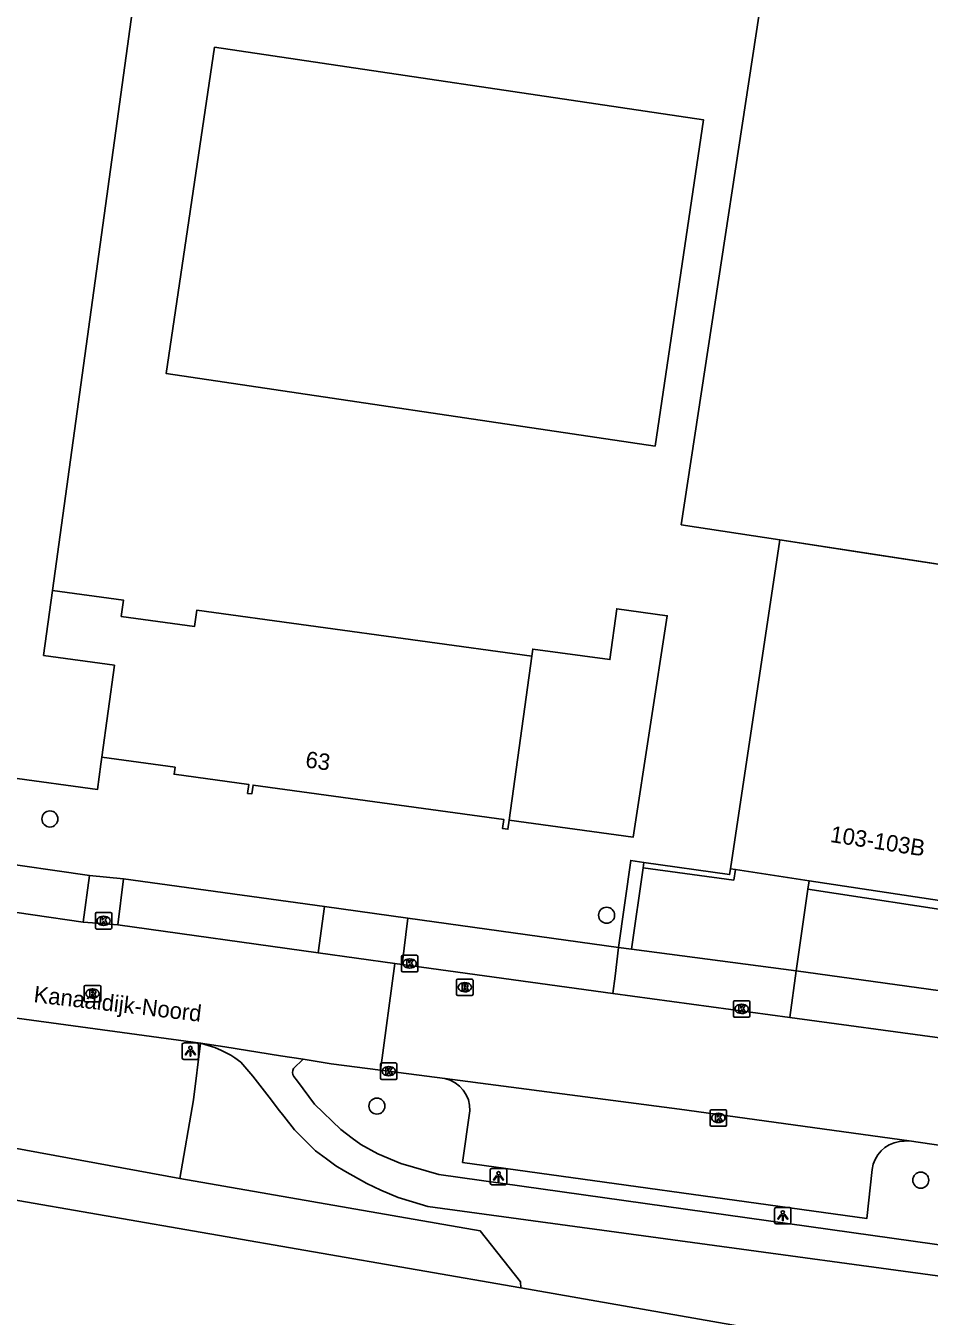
# Model space of a CAD drawing. Extents: x 163010 to 163853, y 382793 to 383982.
# Drawn here: x 163317.7 to 163372.7, y 382836.4 to 382915 of the extents above; entities that cross this region are included whole.
import ezdxf

# ---------------------------------------------------------------- set-up
doc = ezdxf.new("R2010")
doc.units = 0
for name, color, linetype in [('IMGEO_Boom', 7, 'Continuous'), ('IMGEO_Fietspad_open', 7, 'Continuous'), ('IMGEO_Groenvoorziening', 7, 'Continuous'), ('IMGEO_Hek', 7, 'Continuous'), ('IMGEO_Kolk', 7, 'Continuous'), ('IMGEO_Lichtpunt', 7, 'Continuous'), ('IMGEO_Muur', 7, 'Continuous'), ('IMGEO_Openbare_ruimte_label', 7, 'Continuous'), ('IMGEO_Pand', 7, 'Continuous'), ('IMGEO_Pand_nummerreeks', 7, 'Continuous'), ('IMGEO_Pand_vergunning_verleend', 7, 'Continuous'), ('IMGEO_Parkeervlak_gesloten', 7, 'Continuous'), ('IMGEO_Parkeervlak_open', 7, 'Continuous'), ('IMGEO_Rijbaan_lokaal_open', 7, 'Continuous'), ('IMGEO_Rioolput', 7, 'Continuous'), ('IMGEO_Voetpad_gesloten', 7, 'Continuous'), ('IMGEO_Voetpad_open', 7, 'Continuous'), ('IMGEO_Waterloop', 7, 'Continuous')]:
    doc.layers.add(name, color=color, linetype=linetype)

msp = doc.modelspace()

# ---------------------------------------------------------------- linework, layer by layer
at = {"layer": 'IMGEO_Boom'}
for centre in [(163319.165, 382866.647), (163353.055, 382860.785), (163339.071, 382849.16), (163372.178, 382844.649)]:
    msp.add_circle(centre, 0.489, dxfattribs=at)
at = {"layer": 'IMGEO_Fietspad_open'}
for points in [[(163328.342, 382852.995), (163328.799, 382852.856), (163329.201, 382852.719), (163329.62, 382852.555), (163330.175, 382852.263), (163330.426, 382852.1), (163330.779, 382851.826), (163331.276, 382851.256), (163331.516, 382850.98), (163332.653, 382849.515), (163333.07, 382848.976), (163333.412, 382848.539), (163334.065, 382847.703), (163335.332, 382846.43), (163335.997, 382845.943), (163336.58, 382845.516), (163337.125, 382845.189), (163338.464, 382844.438), (163339.318, 382844.032), (163340.356, 382843.584), (163341.233, 382843.336), (163342.164, 382843.039), (163390.211, 382836.499)], [(163333.993, 382851.453), (163334.575, 382852.01)], [(163499.251, 382822.021), (163494.803, 382822.681), (163390.478, 382838.302), (163342.832, 382844.985), (163340.526, 382845.669), (163339.133, 382846.245), (163338.098, 382846.827), (163337.562, 382847.213), (163336.875, 382847.731), (163335.282, 382849.281), (163334.239, 382850.672), (163334.016, 382850.97)]]:
    msp.add_lwpolyline(points, dxfattribs=at)
msp.add_arc((163334.367, 382851.229), 0.436, 149.04306, 216.40956, dxfattribs=at)
at = {"layer": 'IMGEO_Groenvoorziening'}
msp.add_lwpolyline([(163340.951, 382860.603), (163335.871, 382861.306)], dxfattribs=at)
at = {"layer": 'IMGEO_Hek'}
for points in [[(163353.778, 382858.828), (163354.529, 382864.119)], [(163354.529, 382864.119), (163355.327, 382864.004)]]:
    msp.add_lwpolyline(points, dxfattribs=at)
at = {"layer": 'IMGEO_Kolk'}
for p, q in [((163321.933, 382860.019), (163321.933, 382860.871)), ((163322.008, 382860.945), (163322.86, 382860.945)), ((163322.421, 382860.725), (163322.446, 382860.725)), ((163322.934, 382860.871), (163322.934, 382860.019)), ((163322.86, 382859.945), (163322.008, 382859.945)), ((163322.444, 382860.165), (163322.419, 382860.165)), ((163340.565, 382857.417), (163340.565, 382858.269)), ((163340.64, 382858.343), (163341.492, 382858.343)), ((163341.053, 382858.123), (163341.078, 382858.123)), ((163341.566, 382858.269), (163341.566, 382857.417)), ((163341.492, 382857.343), (163340.64, 382857.343)), ((163341.076, 382857.563), (163341.051, 382857.563)), ((163360.774, 382854.653), (163360.774, 382855.505)), ((163360.849, 382855.579), (163361.701, 382855.579)), ((163361.262, 382855.359), (163361.287, 382855.359)), ((163361.775, 382855.505), (163361.775, 382854.653)), ((163361.701, 382854.579), (163360.849, 382854.579)), ((163361.285, 382854.799), (163361.26, 382854.799)), ((163339.365, 382851.784), (163340.217, 382851.784)), ((163339.29, 382850.858), (163339.29, 382851.71)), ((163339.801, 382851.004), (163339.776, 382851.004)), ((163339.778, 382851.564), (163339.803, 382851.564)), ((163340.291, 382851.71), (163340.291, 382850.858)), ((163340.217, 382850.784), (163339.365, 382850.784)), ((163359.355, 382848.013), (163359.355, 382848.865)), ((163359.43, 382848.939), (163360.282, 382848.939)), ((163359.843, 382848.719), (163359.868, 382848.719)), ((163360.356, 382848.865), (163360.356, 382848.013)), ((163360.282, 382847.939), (163359.43, 382847.939)), ((163359.866, 382848.159), (163359.841, 382848.159))]:
    msp.add_line(p, q, dxfattribs=at)
for points in [[(163321.933, 382860.019), (163321.933, 382860.871)], [(163322.008, 382860.945), (163322.86, 382860.945)], [(163322.254, 382860.645), (163322.377, 382860.645), (163322.377, 382860.494), (163322.507, 382860.645), (163322.671, 382860.645), (163322.525, 382860.494), (163322.678, 382860.245), (163322.526, 382860.245), (163322.441, 382860.409), (163322.377, 382860.342), (163322.377, 382860.245), (163322.254, 382860.245), (163322.254, 382860.645)], [(163322.934, 382860.871), (163322.934, 382860.019)], [(163322.86, 382859.945), (163322.008, 382859.945)], [(163340.565, 382857.417), (163340.565, 382858.269)], [(163340.64, 382858.343), (163341.492, 382858.343)], [(163341.566, 382858.269), (163341.566, 382857.417)], [(163341.492, 382857.343), (163340.64, 382857.343)], [(163340.886, 382858.043), (163341.009, 382858.043), (163341.009, 382857.892), (163341.139, 382858.043), (163341.303, 382858.043), (163341.157, 382857.892), (163341.31, 382857.643), (163341.158, 382857.643), (163341.073, 382857.807), (163341.009, 382857.74), (163341.009, 382857.643), (163340.886, 382857.643), (163340.886, 382858.043)], [(163360.774, 382854.653), (163360.774, 382855.505)], [(163360.849, 382855.579), (163361.701, 382855.579)], [(163361.095, 382855.279), (163361.218, 382855.279), (163361.218, 382855.128), (163361.348, 382855.279), (163361.512, 382855.279), (163361.366, 382855.128), (163361.519, 382854.879), (163361.367, 382854.879), (163361.282, 382855.043), (163361.218, 382854.976), (163361.218, 382854.879), (163361.095, 382854.879), (163361.095, 382855.279)], [(163361.775, 382855.505), (163361.775, 382854.653)], [(163361.701, 382854.579), (163360.849, 382854.579)], [(163339.365, 382851.784), (163340.217, 382851.784)], [(163339.29, 382850.858), (163339.29, 382851.71)], [(163339.611, 382851.484), (163339.734, 382851.484), (163339.734, 382851.333), (163339.864, 382851.484), (163340.028, 382851.484), (163339.882, 382851.333), (163340.035, 382851.084), (163339.883, 382851.084), (163339.798, 382851.248), (163339.734, 382851.181), (163339.734, 382851.084), (163339.611, 382851.084), (163339.611, 382851.484)], [(163340.291, 382851.71), (163340.291, 382850.858)], [(163340.217, 382850.784), (163339.365, 382850.784)], [(163359.355, 382848.013), (163359.355, 382848.865)], [(163359.43, 382848.939), (163360.282, 382848.939)], [(163359.676, 382848.639), (163359.799, 382848.639), (163359.799, 382848.488), (163359.929, 382848.639), (163360.093, 382848.639), (163359.947, 382848.488), (163360.1, 382848.239), (163359.948, 382848.239), (163359.863, 382848.403), (163359.799, 382848.336), (163359.799, 382848.239), (163359.676, 382848.239), (163359.676, 382848.639)], [(163360.356, 382848.865), (163360.356, 382848.013)], [(163360.282, 382847.939), (163359.43, 382847.939)]]:
    msp.add_lwpolyline(points, dxfattribs=at)
for centre, start, end in [((163322.01, 382860.869), 91.55205, 178.44795), ((163322.01, 382860.869), 91.55205, 178.44795), ((163322.858, 382860.869), 1.55205, 88.44795), ((163322.858, 382860.869), 1.55205, 88.44795), ((163322.01, 382860.021), 181.55205, 268.44795), ((163322.01, 382860.021), 181.55205, 268.44795), ((163322.858, 382860.021), 271.55205, 358.44795), ((163322.858, 382860.021), 271.55205, 358.44795), ((163340.642, 382858.267), 91.55205, 178.44795), ((163340.642, 382858.267), 91.55205, 178.44795), ((163341.49, 382858.267), 1.55205, 88.44795), ((163341.49, 382858.267), 1.55205, 88.44795), ((163340.642, 382857.419), 181.55205, 268.44795), ((163340.642, 382857.419), 181.55205, 268.44795), ((163341.49, 382857.419), 271.55205, 358.44795), ((163341.49, 382857.419), 271.55205, 358.44795), ((163360.851, 382855.503), 91.55205, 178.44795), ((163360.851, 382855.503), 91.55205, 178.44795), ((163361.699, 382855.503), 1.55205, 88.44795), ((163361.699, 382855.503), 1.55205, 88.44795), ((163360.851, 382854.655), 181.55205, 268.44795), ((163360.851, 382854.655), 181.55205, 268.44795), ((163361.699, 382854.655), 271.55205, 358.44795), ((163361.699, 382854.655), 271.55205, 358.44795), ((163339.367, 382851.708), 91.55205, 178.44795), ((163339.367, 382851.708), 91.55205, 178.44795), ((163340.215, 382851.708), 1.55205, 88.44795), ((163340.215, 382851.708), 1.55205, 88.44795), ((163339.367, 382850.86), 181.55205, 268.44795), ((163339.367, 382850.86), 181.55205, 268.44795), ((163340.215, 382850.86), 271.55205, 358.44795), ((163340.215, 382850.86), 271.55205, 358.44795), ((163359.432, 382848.863), 91.55205, 178.44795), ((163359.432, 382848.863), 91.55205, 178.44795), ((163360.28, 382848.863), 1.55205, 88.44795), ((163360.28, 382848.863), 1.55205, 88.44795), ((163359.432, 382848.015), 181.55205, 268.44795), ((163359.432, 382848.015), 181.55205, 268.44795), ((163360.28, 382848.015), 271.55205, 358.44795), ((163360.28, 382848.015), 271.55205, 358.44795)]:
    msp.add_arc(centre, 0.0765, start, end, dxfattribs=at)
for centre, major_axis, ratio, start_param, end_param in [((163322.42, 382860.445), (-0.387, 0.002), 0.722429, 4.712389, 7.853982), ((163322.445, 382860.445), (-0.39, 0.002), 0.717154, 1.570796, 4.712389), ((163341.052, 382857.843), (-0.387, 0.002), 0.722429, 4.712389, 7.853982), ((163341.077, 382857.843), (-0.39, 0.002), 0.717154, 1.570796, 4.712389), ((163361.261, 382855.079), (-0.387, 0.002), 0.722429, 4.712389, 7.853982), ((163361.286, 382855.079), (-0.39, 0.002), 0.717154, 1.570796, 4.712389), ((163339.777, 382851.284), (-0.387, 0.002), 0.722429, 4.712389, 7.853982), ((163339.802, 382851.284), (-0.39, 0.002), 0.717154, 1.570796, 4.712389), ((163359.842, 382848.439), (-0.387, 0.002), 0.722429, 4.712389, 7.853982), ((163359.867, 382848.439), (-0.39, 0.002), 0.717154, 1.570796, 4.712389)]:
    msp.add_ellipse(centre, major_axis=major_axis, ratio=ratio, start_param=start_param, end_param=end_param, dxfattribs=at)
at = {"layer": 'IMGEO_Lichtpunt'}
for p, q in [((163327.219, 382852.907), (163327.219, 382852.1)), ((163327.219, 382852.907), (163327.219, 382852.1)), ((163328.121, 382853.002), (163327.313, 382853.002)), ((163328.121, 382853.002), (163327.313, 382853.002)), ((163328.215, 382852.1), (163328.215, 382852.907)), ((163328.215, 382852.1), (163328.215, 382852.907)), ((163327.313, 382852.006), (163328.121, 382852.006)), ((163327.313, 382852.006), (163328.121, 382852.006)), ((163345.976, 382845.27), (163345.976, 382844.463)), ((163345.976, 382845.27), (163345.976, 382844.463)), ((163346.878, 382845.365), (163346.07, 382845.365)), ((163346.878, 382845.365), (163346.07, 382845.365)), ((163346.972, 382844.463), (163346.972, 382845.27)), ((163346.972, 382844.463), (163346.972, 382845.27)), ((163346.07, 382844.369), (163346.878, 382844.369)), ((163346.07, 382844.369), (163346.878, 382844.369)), ((163363.281, 382842.891), (163363.281, 382842.084)), ((163363.281, 382842.891), (163363.281, 382842.084)), ((163364.183, 382842.986), (163363.375, 382842.986)), ((163364.183, 382842.986), (163363.375, 382842.986)), ((163364.277, 382842.084), (163364.277, 382842.891)), ((163364.277, 382842.084), (163364.277, 382842.891)), ((163363.375, 382841.99), (163364.183, 382841.99)), ((163363.375, 382841.99), (163364.183, 382841.99))]:
    msp.add_line(p, q, dxfattribs=at)
for points in [[(163327.593, 382852.571), (163327.632, 382852.543), (163327.444, 382852.281), (163327.406, 382852.308), (163327.593, 382852.571)], [(163327.805, 382852.543), (163327.843, 382852.57), (163328.03, 382852.308), (163327.991, 382852.28), (163327.805, 382852.543)], [(163327.695, 382852.523), (163327.742, 382852.523), (163327.742, 382852.201), (163327.695, 382852.201), (163327.695, 382852.523)], [(163346.35, 382844.934), (163346.389, 382844.906), (163346.201, 382844.644), (163346.163, 382844.671), (163346.35, 382844.934)], [(163346.452, 382844.886), (163346.499, 382844.886), (163346.499, 382844.564), (163346.452, 382844.564), (163346.452, 382844.886)], [(163346.562, 382844.906), (163346.6, 382844.933), (163346.787, 382844.671), (163346.748, 382844.643), (163346.562, 382844.906)], [(163363.655, 382842.555), (163363.694, 382842.527), (163363.506, 382842.265), (163363.468, 382842.292), (163363.655, 382842.555)], [(163363.757, 382842.507), (163363.804, 382842.507), (163363.804, 382842.185), (163363.757, 382842.185), (163363.757, 382842.507)], [(163363.867, 382842.527), (163363.905, 382842.554), (163364.092, 382842.292), (163364.053, 382842.264), (163363.867, 382842.527)]]:
    msp.add_lwpolyline(points, dxfattribs=at)
for centre in [(163327.718, 382852.705), (163346.475, 382845.068), (163363.78, 382842.689)]:
    msp.add_circle(centre, 0.0994, dxfattribs=at)
for centre, start, end in [((163327.313, 382852.907), 90, 180), ((163327.313, 382852.907), 90, 180), ((163328.121, 382852.907), 0, 90), ((163328.121, 382852.907), 0, 90), ((163327.313, 382852.1), 180, 270), ((163327.313, 382852.1), 180, 270), ((163328.121, 382852.1), 270, 0), ((163328.121, 382852.1), 270, 360), ((163346.07, 382845.27), 90, 180), ((163346.07, 382845.27), 90, 180), ((163346.878, 382845.27), 0, 90), ((163346.878, 382845.27), 0, 90), ((163346.07, 382844.463), 180, 270), ((163346.07, 382844.463), 180, 270), ((163346.878, 382844.463), 270, 0), ((163346.878, 382844.463), 270, 360), ((163363.375, 382842.891), 90, 180), ((163363.375, 382842.891), 90, 180), ((163364.183, 382842.891), 0, 90), ((163364.183, 382842.891), 0, 90), ((163363.375, 382842.084), 180, 270), ((163363.375, 382842.084), 180, 270), ((163364.183, 382842.084), 270, 0), ((163364.183, 382842.084), 270, 360)]:
    msp.add_arc(centre, 0.0946, start, end, dxfattribs=at)
at = {"layer": 'IMGEO_Muur'}
for points in [[(163355.278, 382863.668), (163355.327, 382864.004)], [(163360.906, 382863.566), (163360.796, 382862.924), (163355.278, 382863.668)], [(163355.327, 382864.004), (163360.543, 382863.256), (163360.594, 382863.613)]]:
    msp.add_lwpolyline(points, dxfattribs=at)
at = {"layer": 'IMGEO_Pand'}
for points in [[(163304.014, 382919.313), (163303.527, 382919.38), (163298.081, 382879.782), (163296.449, 382880.006), (163296.043, 382877.058), (163295.362, 382872.104), (163322.054, 382868.433), (163322.268, 382869.988), (163322.327, 382870.414)], [(163319.328, 382880.568), (163324.274, 382916.519)], [(163356.004, 382889.354), (163358.959, 382909.225), (163329.194, 382913.651), (163326.239, 382893.78), (163356.004, 382889.354)], [(163380.343, 382860.625), (163383.283, 382880.62), (163378.143, 382881.412), (163363.598, 382883.652), (163360.594, 382863.613)], [(163319.328, 382880.568), (163318.783, 382876.605), (163323.097, 382876.012), (163322.327, 382870.414)], [(163348.498, 382876.556), (163328.1, 382879.361), (163327.964, 382878.37), (163323.506, 382878.984), (163323.642, 382879.974), (163319.328, 382880.568)], [(163347.125, 382866.569), (163354.664, 382865.532), (163356.747, 382879.026), (163353.676, 382879.448), (163353.251, 382876.354), (163348.559, 382876.999), (163348.498, 382876.556)], [(163347.125, 382866.569), (163348.498, 382876.556)], [(163322.327, 382870.414), (163326.785, 382869.801), (163326.726, 382869.374), (163331.274, 382868.749), (163331.2, 382868.206), (163331.457, 382868.17), (163331.531, 382868.713), (163346.788, 382866.615), (163346.714, 382866.071), (163347.05, 382866.025), (163347.125, 382866.569)], [(163360.594, 382863.613), (163360.906, 382863.566)], [(163360.906, 382863.566), (163365.381, 382862.889)], [(163365.381, 382862.889), (163375.465, 382861.363)]]:
    msp.add_lwpolyline(points, dxfattribs=at)
at = {"layer": 'IMGEO_Pand_vergunning_verleend'}
msp.add_lwpolyline([(163357.603, 382884.564), (163363.572, 382923.804), (163395.053, 382919.015), (163389.045, 382879.732), (163383.283, 382880.62), (163378.143, 382881.412), (163368.833, 382882.846), (163363.598, 382883.652), (163357.603, 382884.564)], dxfattribs=at)
at = {"layer": 'IMGEO_Parkeervlak_gesloten'}
for points in [[(163369.23, 382845.292), (163368.886, 382842.312), (163344.285, 382845.732), (163344.737, 382848.861)], [(163371.466, 382847.039), (163370.881, 382847.001)]]:
    msp.add_lwpolyline(points, dxfattribs=at)
for centre, radius, start, end in [((163342.772, 382848.916), 1.966, 358.39274, 77.41749), ((163371.143, 382845.096), 1.923, 97.83478, 174.14309)]:
    msp.add_arc(centre, radius, start, end, dxfattribs=at)
at = {"layer": 'IMGEO_Parkeervlak_open'}
for points in [[(163315.361, 382864.096), (163321.573, 382863.211)], [(163335.871, 382861.306), (163323.643, 382862.998)], [(163335.505, 382858.5), (163335.871, 382861.306)], [(163340.612, 382857.792), (163340.951, 382860.603)], [(163353.778, 382858.828), (163340.951, 382860.603)]]:
    msp.add_lwpolyline(points, dxfattribs=at)
at = {"layer": 'IMGEO_Rijbaan_lokaal_open'}
for points in [[(163321.191, 382860.36), (163315.036, 382861.25)], [(163323.304, 382860.193), (163321.756, 382860.315), (163321.191, 382860.36)], [(163323.304, 382860.193), (163335.505, 382858.5)], [(163335.505, 382858.5), (163340.163, 382857.854)], [(163340.163, 382857.854), (163339.297, 382851.346)], [(163340.612, 382857.792), (163340.163, 382857.854)], [(163353.433, 382856.013), (163340.612, 382857.792)], [(163364.208, 382854.552), (163353.433, 382856.013)], [(163317.148, 382854.52), (163328.342, 382852.995)], [(163374.305, 382853.173), (163373.479, 382853.29), (163364.208, 382854.552)], [(163334.575, 382852.01), (163333.199, 382852.227), (163329.807, 382852.762), (163328.342, 382852.995)], [(163339.297, 382851.346), (163336.294, 382851.738), (163334.575, 382852.01)], [(163343.2, 382850.835), (163339.297, 382851.346)], [(163343.2, 382850.835), (163357.498, 382848.967), (163371.466, 382847.039)], [(163374.384, 382846.613), (163371.466, 382847.039)]]:
    msp.add_lwpolyline(points, dxfattribs=at)
at = {"layer": 'IMGEO_Rioolput'}
for p, q in [((163321.333, 382856.513), (163322.185, 382856.513)), ((163343.92, 382855.973), (163343.92, 382856.825)), ((163343.995, 382856.899), (163344.847, 382856.899)), ((163344.408, 382856.679), (163344.433, 382856.679)), ((163344.921, 382856.825), (163344.921, 382855.973)), ((163321.258, 382855.587), (163321.258, 382856.439)), ((163321.769, 382855.733), (163321.744, 382855.733)), ((163321.746, 382856.293), (163321.771, 382856.293)), ((163322.259, 382856.439), (163322.259, 382855.587)), ((163344.847, 382855.899), (163343.995, 382855.899)), ((163344.431, 382856.119), (163344.406, 382856.119)), ((163322.185, 382855.513), (163321.333, 382855.513))]:
    msp.add_line(p, q, dxfattribs=at)
for points in [[(163321.333, 382856.513), (163322.185, 382856.513)], [(163343.92, 382855.973), (163343.92, 382856.825)], [(163343.995, 382856.899), (163344.847, 382856.899)], [(163344.509, 382856.597), (163344.257, 382856.599), (163344.257, 382856.199)], [(163344.435, 382856.518), (163344.381, 382856.518), (163344.381, 382856.437)], [(163344.921, 382856.825), (163344.921, 382855.973)], [(163321.258, 382855.587), (163321.258, 382856.439)], [(163321.847, 382856.211), (163321.595, 382856.213), (163321.595, 382855.813)], [(163321.595, 382855.813), (163321.719, 382855.813), (163321.719, 382855.975), (163321.73, 382855.975)], [(163321.773, 382856.132), (163321.719, 382856.132), (163321.719, 382856.051)], [(163321.719, 382856.051), (163321.771, 382856.051)], [(163321.777, 382855.946), (163321.848, 382855.813), (163321.988, 382855.813), (163321.923, 382855.939)], [(163322.259, 382856.439), (163322.259, 382855.587)], [(163344.847, 382855.899), (163343.995, 382855.899)], [(163344.257, 382856.199), (163344.381, 382856.199), (163344.381, 382856.361), (163344.392, 382856.361)], [(163344.381, 382856.437), (163344.433, 382856.437)], [(163344.439, 382856.332), (163344.51, 382856.199), (163344.65, 382856.199), (163344.585, 382856.325)], [(163322.185, 382855.513), (163321.333, 382855.513)]]:
    msp.add_lwpolyline(points, dxfattribs=at)
for centre, radius, start, end in [((163321.335, 382856.437), 0.0765, 91.55205, 178.44795), ((163321.335, 382856.437), 0.0765, 91.55205, 178.44795), ((163322.183, 382856.437), 0.0765, 1.55205, 88.44795), ((163322.183, 382856.437), 0.0765, 1.55205, 88.44795), ((163343.997, 382856.823), 0.0765, 91.55205, 178.44795), ((163343.997, 382856.823), 0.0765, 91.55205, 178.44795), ((163344.441, 382856.422), 0.0964, 77.00612, 93.18647), ((163344.455, 382856.479), 0.0378, 276.66336, 79.67722), ((163344.508, 382856.487), 0.109, 350.36119, 89.41601), ((163344.845, 382856.823), 0.0765, 1.55205, 88.44795), ((163344.845, 382856.823), 0.0765, 1.55205, 88.44795), ((163321.729, 382855.922), 0.0533, 26.02933, 88.69889), ((163321.755, 382856.24), 0.19, 274.7715, 282.96867), ((163321.779, 382856.036), 0.0964, 77.00612, 93.18647), ((163321.793, 382856.093), 0.0378, 276.66336, 79.67722), ((163321.846, 382856.101), 0.109, 350.36119, 89.41601), ((163321.844, 382856.101), 0.112, 277.58423, 350.98172), ((163321.828, 382855.886), 0.108, 29.51342, 73.79051), ((163343.997, 382855.975), 0.0765, 181.55205, 268.44795), ((163343.997, 382855.975), 0.0765, 181.55205, 268.44795), ((163344.391, 382856.308), 0.0533, 26.02933, 88.69889), ((163344.417, 382856.626), 0.19, 274.7715, 282.96867), ((163344.506, 382856.487), 0.112, 277.58423, 350.98172), ((163344.49, 382856.272), 0.108, 29.51342, 73.79051), ((163344.845, 382855.975), 0.0765, 271.55205, 358.44795), ((163344.845, 382855.975), 0.0765, 271.55205, 358.44795), ((163321.335, 382855.589), 0.0765, 181.55205, 268.44795), ((163321.335, 382855.589), 0.0765, 181.55205, 268.44795), ((163322.183, 382855.589), 0.0765, 271.55205, 358.44795), ((163322.183, 382855.589), 0.0765, 271.55205, 358.44795)]:
    msp.add_arc(centre, radius, start, end, dxfattribs=at)
for centre, major_axis, ratio, start_param, end_param in [((163344.407, 382856.399), (-0.387, 0.002), 0.722429, 4.712389, 7.853982), ((163344.432, 382856.399), (-0.39, 0.002), 0.717154, 1.570796, 4.712389), ((163321.745, 382856.013), (-0.387, 0.002), 0.722429, 4.712389, 7.853982), ((163321.77, 382856.013), (-0.39, 0.002), 0.717154, 1.570796, 4.712389)]:
    msp.add_ellipse(centre, major_axis=major_axis, ratio=ratio, start_param=start_param, end_param=end_param, dxfattribs=at)
at = {"layer": 'IMGEO_Voetpad_gesloten'}
for points in [[(163327.083, 382844.752), (163315.914, 382846.807)], [(163327.083, 382844.752), (163345.365, 382841.56), (163347.815, 382838.449), (163347.839, 382838.095)], [(163347.839, 382838.095), (163316.289, 382843.564), (163315.348, 382843.727)]]:
    msp.add_lwpolyline(points, dxfattribs=at)
at = {"layer": 'IMGEO_Voetpad_open'}
for points in [[(163353.778, 382858.828), (163354.529, 382864.119), (163355.327, 382864.004)], [(163354.56, 382858.724), (163355.278, 382863.668)], [(163321.573, 382863.211), (163321.191, 382860.36)], [(163321.573, 382863.211), (163323.643, 382862.998)], [(163323.643, 382862.998), (163323.304, 382860.193)], [(163365.381, 382862.889), (163365.307, 382862.378)], [(163365.307, 382862.378), (163364.585, 382857.4)], [(163365.307, 382862.378), (163375.396, 382860.833)], [(163353.433, 382856.013), (163353.582, 382857.082), (163353.778, 382858.828)], [(163353.778, 382858.828), (163354.56, 382858.724)], [(163354.56, 382858.724), (163364.585, 382857.4)], [(163364.208, 382854.552), (163364.585, 382857.4)], [(163364.585, 382857.4), (163374.693, 382855.989)], [(163328.342, 382852.995), (163327.911, 382849.547), (163327.083, 382844.752)]]:
    msp.add_lwpolyline(points, dxfattribs=at)
at = {"layer": 'IMGEO_Waterloop'}
msp.add_lwpolyline([(163685.611, 382793.195), (163685.611, 382793.195), (163685.451, 382793.218), (163644.684, 382799.5), (163532.552, 382816.044), (163514.398, 382818.897), (163500, 382817.915), (163490.933, 382817.132), (163485.145, 382816.814), (163483.656, 382816.879), (163421.963, 382825.134), (163407.316, 382827.646), (163347.839, 382838.095)], dxfattribs=at)

# ---------------------------------------------------------------- texts
at = {"layer": 'IMGEO_Openbare_ruimte_label'}
msp.add_text('Kanaaldijk-Noord', height=1, rotation=353.28012, dxfattribs=at).set_placement((163318.142, 382855.494))
msp.add_text('Kanaaldijk-Noord', height=1, rotation=353.28012, dxfattribs=at).set_placement((163318.142, 382855.494))
at = {"layer": 'IMGEO_Pand_nummerreeks'}
for s, rotation, p in [('63', 352.16767, (163334.68, 382869.794)), ('103-103B', 351.22802, (163366.623, 382865.25))]:
    msp.add_text(s, height=1, rotation=rotation, dxfattribs=at).set_placement(p)

doc.saveas('drawing.dxf')
